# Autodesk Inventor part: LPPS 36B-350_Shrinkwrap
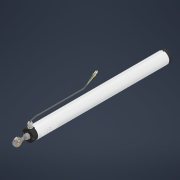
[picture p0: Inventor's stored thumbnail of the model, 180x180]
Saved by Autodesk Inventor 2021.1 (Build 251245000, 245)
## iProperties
Created: 2020-09
Part Number: LPPS 36B-350_Shrinkwrap
Material: Generic
Document SubType Name: Modeling
Designer: J. Nielson
Density: 1 g/cm^3
Appearance: Default
Author: J. Nielson
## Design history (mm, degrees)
derived "LPPS 36B-350.iam"
body "Solid1"
node "LPPS 36B Cable End Cap.iam:1::LPPS-36B PLASTIC CABLE END.ipt"
node "LPPS 36B Cable End Cap.iam:1::LPPS 36B- Cable Gland.ipt:1"
body "Solid2"
node "LPPS 36B Cable End Cap.iam:1::Cable Gland Cap.ipt:1"
body "Solid3"
node "LPPS 36B Cable End Cap.iam:1::Cable.ipt:1"
body "Solid4"
node "LPPS 36B Cable End Cap.iam:1::Cable Gland Seal 1 of 2.ipt:1"
body "Solid5"
node "LPPS 36B Cable End Cap.iam:1::Cable Gland 2 of 2.ipt:1"
body "Solid6"
node "LPPS 36B Cable End Cap.iam:1::#6 Terminal Ring 22 - 18 AWG.i"
body "Solid7"
node "LPPS-36-350 METAL HOUSING.ipt:1"
body "Solid8"
node "MALE Rod Eye SW.ipt:1"
body "Solid9"
node "LPPS-36B PLASTIC STROKE END.ipt:1"
body "Solid10"
node "LPPS 36B-350 Back Stop.ipt:1"
body "Solid11"
node "LPPS 36B 350 Front Stop.ipt:1"
body "Solid12"
node "AS 1427 - M3 x 16.ipt:1"
body "Solid13"
node "AS 1427 - M3 x 16.ipt:2"
body "Solid14"
node "AS 1427 - M3 x 16.ipt:3"
body "Solid15"
node "AS 1427 - M3 x 16.ipt:4"
body "Solid16"
node "AS 1112 - M8  Type 5.ipt:1"
body "Solid17"
node "AS 1968 - 1976 - 8.ipt:1"
body "Solid18"
node "AS 1237 - 8.ipt:1"
body "Solid19"
